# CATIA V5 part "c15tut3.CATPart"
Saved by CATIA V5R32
Part number: Part1
Bounding box of the stored display mesh (mm): x -75 to 75, y -40 to 40, z 0 to 5
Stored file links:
  D:\PROJECTS\Project 2022\CATIA V5 6R 2022\Resources\Tutorial Files\c15_catia_v5_6r2022_tut\c15tut3.CATPart
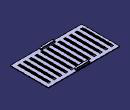
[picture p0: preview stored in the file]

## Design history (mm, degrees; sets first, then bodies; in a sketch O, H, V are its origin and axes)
SheetMetalParameters1: Thickness 1, BendRadius 2, KFactor 0.400515 {= log(min(100,max(20*SheetMetalParameters1.BendRadius,SheetMetalParameters1.Thickness)/SheetMetalParameters1.Thickness))/log(100)/2}, ReliefRadialLength 1, ReliefAxialLength 2, MinimumBendRadius 0
Body1 (main body)
  Sketch1 on xy-plane, origin (0, 0, 0), H (1, 0, 0), V (0, 1, 0)
    line L1 (75, 40) -> (75, -40)
    line L2 (75, -40) -> (-75, -40)
    line L3 (-75, -40) -> (-75, 40)
    line L4 (-75, 40) -> (75, 40)
    length L4 = 150
    length L1 = 80
    vertical: L1 V, L3 V
    horizontal: L2 H, L4 H
    equidistance: L1 L3 O, L2 L4 O
  Wall1: Thickness 1, Profile Sketch1
  Sketch2 on face of Wall1, origin (0, 0, 0), H (1, 0, 0), V (0, 1, 0)
    line L1 (64.5, 30) -> (67, 30)
    line L2 (67, 30) -> (67, -30)
    line L3 (67, -30) -> (64.5, -30)
    line L4 (64.5, -30) -> (64.5, 30)
    reference projected line E1 (75, 40) -> (75, -40) from edge [face of Wall1 | face of Wall1]
    reference projected line E2 (-75, 40) -> (75, 40) from edge [face of Wall1 | face of Wall1]
    length L2 = 60
    distance L2 L4 = 2.5
    distance E1 L2 = 8
    distance L1 E2 = 10
    horizontal: L1 H, L3 H
    vertical: L2 V, L4 V
  d_Stamp1: NewRoot_AttribNormalisation "No Standard", Stamp_FilletRadius 2
  RectPattern1: of d_Stamp1, direction 1 instances 12, spacing 12, along face of Wall1 reversed
  Sketch3 on face of Wall1, origin (0, 0, 0), H (1, 0, 0), V (0, -1, 0)
    point P1 (0, 36.5)
    reference projected line E1 (75, 40) -> (75, -40) from edge [face of Wall1 | face of Wall1]
    reference projected line E2 (-75, 40) -> (75, 40) from edge [face of Wall1 | face of Wall1]
    distance P1 E1 = 75
    distance P1 E2 = 3.5
  Sketch4 on face of Wall1, origin (0, -36.5, 0), H (1, 0, 0), V (0, 1, 0)
    point P1 (0, 0)
    reference projected point E1 (0, 0) from Sketch3.P1
    coincidence: E1 P1
  d_Stamp2: NewRoot_AttribNormalisation "No Standard", Stamp_FilletRadius 0.5
  SHM_Mirror1: MirroringPlane zx-plane, ObjectToMirror d_Stamp2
